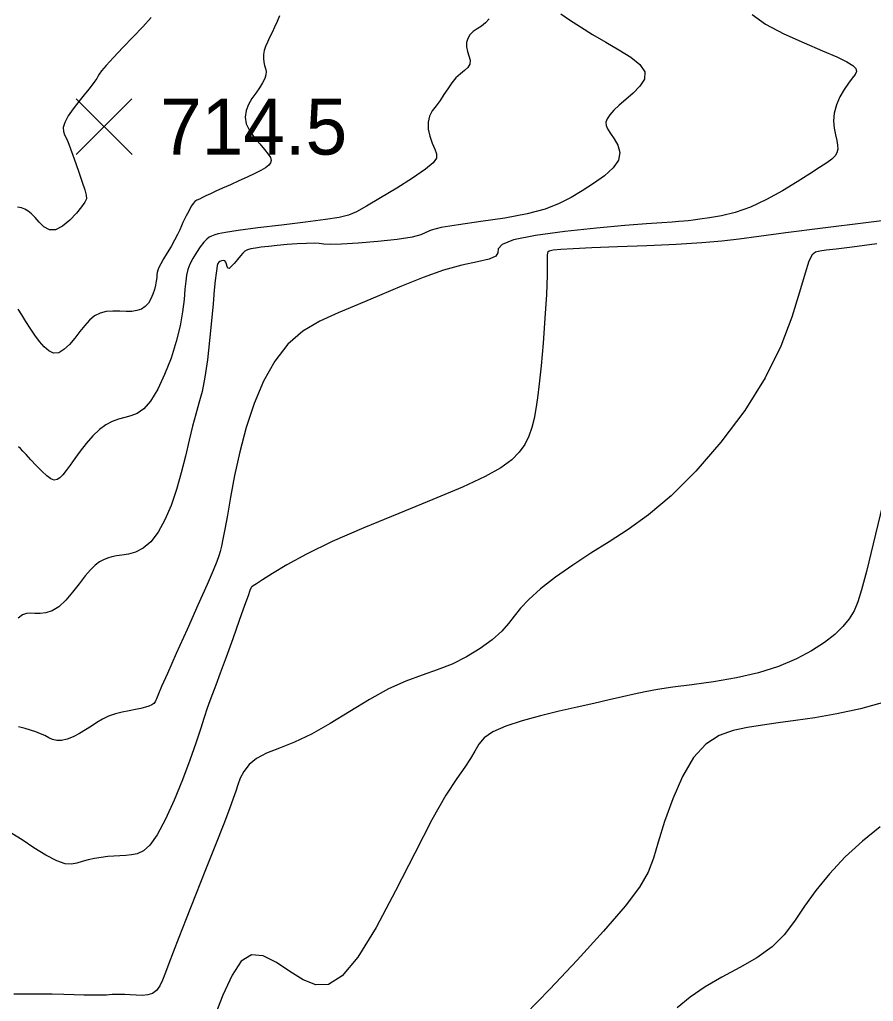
# Model space of a CAD drawing. Extents: x 2566142 to 2571431, y 418755 to 421584.
# Drawn here: x 2567768.3 to 2567997.3, y 419211.1 to 419474.5 of the extents above; entities that cross this region are included whole.
import ezdxf

# ---------------------------------------------------------------- set-up
doc = ezdxf.new("R2010")
doc.units = 0
for name, color, linetype in [('Contour_ADS_Major', 7, 'Continuous'), ('Contour_ADS_Minor', 7, 'Continuous'), ('Contour_ADS_Spot_Elevation', 7, 'Continuous')]:
    doc.layers.add(name, color=color, linetype=linetype)

# ---------------------------------------------------------------- blocks, each defined once
blk = doc.blocks.new('S750')
at = {"layer": 'Contour_ADS_Spot_Elevation'}
for p, q in [((-0.5, 0.498), (0.5, -0.498)), ((-0.498, -0.5), (0.498, 0.5))]:
    blk.add_line(p, q, dxfattribs=at)

msp = doc.modelspace()

# ---------------------------------------------------------------- linework, layer by layer
at = {"layer": 'Contour_ADS_Major'}
for points in [[(2567913.5, 419476), (2567915.82, 419474.42), (2567918.7, 419472.54), (2567921.98, 419470.49), (2567925.49, 419468.4), (2567929.03, 419466.37), (2567932.23, 419464.38), (2567934.69, 419462.43), (2567936, 419460.48), (2567935.89, 419458.53), (2567934.68, 419456.61), (2567932.85, 419454.76), (2567930.86, 419453.05), (2567929.1, 419451.5), (2567927.67, 419450.13), (2567926.59, 419448.92), (2567925.88, 419447.87), (2567925.55, 419446.96), (2567925.6, 419446.08), (2567926.01, 419445.12), (2567926.78, 419443.95), (2567927.81, 419442.49), (2567928.79, 419440.77), (2567929.31, 419438.85), (2567928.97, 419436.8), (2567927.5, 419434.69), (2567925.14, 419432.58), (2567922.26, 419430.51), (2567919.2, 419428.55), (2567916.22, 419426.74), (2567913.03, 419425.09), (2567909.23, 419423.62), (2567904.43, 419422.33), (2567898.45, 419421.22), (2567892, 419420.26), (2567885.99, 419419.43), (2567881.36, 419418.67), (2567878.7, 419417.98), (2567877.25, 419417.32), (2567875.92, 419416.69), (2567873.6, 419416.07)], [(2567873.6, 419416.07), (2567869.56, 419415.46), (2567864.41, 419414.91), (2567859.12, 419414.47), (2567854.66, 419414.21), (2567851.72, 419414.17), (2567849.94, 419414.26), (2567848.67, 419414.4), (2567847.27, 419414.48), (2567845.25, 419414.44), (2567842.75, 419414.3), (2567840.04, 419414.09), (2567837.4, 419413.86), (2567835.08, 419413.63), (2567833.13, 419413.41), (2567831.53, 419413.18), (2567830.3, 419412.94), (2567829.4, 419412.67), (2567828.73, 419412.31), (2567828.15, 419411.8), (2567827.51, 419411.07), (2567826.73, 419410.1), (2567825.89, 419409.07), (2567825.09, 419408.21), (2567824.48, 419407.74), (2567824.12, 419407.81), (2567823.94, 419408.27), (2567823.83, 419408.88), (2567823.65, 419409.43), (2567823.33, 419409.73), (2567822.9, 419409.8), (2567822.44, 419409.72), (2567822.03, 419409.56), (2567821.73, 419409.36), (2567821.51, 419409.05), (2567821.33, 419408.53), (2567821.18, 419407.68), (2567821, 419406.4), (2567820.79, 419404.51), (2567820.52, 419401.85), (2567820.18, 419398.24), (2567819.76, 419393.62), (2567819.25, 419388.42), (2567818.66, 419383.2), (2567817.98, 419378.5), (2567817.23, 419374.71), (2567816.41, 419371.56), (2567815.55, 419368.6), (2567814.66, 419365.4), (2567813.74, 419361.62), (2567812.76, 419357.38), (2567811.67, 419352.91), (2567810.41, 419348.42), (2567808.93, 419344.14), (2567807.27, 419340.26), (2567805.45, 419336.94), (2567803.5, 419334.37), (2567801.45, 419332.65), (2567799.41, 419331.64), (2567797.47, 419331.1), (2567795.72, 419330.82), (2567794.25, 419330.59), (2567793, 419330.35), (2567791.89, 419330.03), (2567790.82, 419329.58), (2567789.73, 419328.96), (2567788.56, 419328.07), (2567787.29, 419326.85), (2567785.86, 419325.21), (2567784.25, 419323.14), (2567782.51, 419320.88), (2567780.7, 419318.72), (2567778.87, 419316.97), (2567777.07, 419315.86), (2567775.36, 419315.29), (2567773.79, 419315.11), (2567772.4, 419315.14), (2567771.23, 419315.21), (2567770.16, 419315.15), (2567769.09, 419314.77), (2567767.89, 419313.87)], [(2568000.29, 419291.32), (2567993.82, 419289.55), (2567987.49, 419288.21), (2567981.61, 419287.19), (2567976.4, 419286.41), (2567971.77, 419285.77), (2567967.55, 419285.18), (2567963.57, 419284.54), (2567959.69, 419283.72), (2567955.94, 419282.37), (2567952.39, 419280.11), (2567949.08, 419276.53), (2567946.09, 419271.45), (2567943.48, 419265.45), (2567941.29, 419259.32), (2567939.6, 419253.82), (2567938.32, 419249.49), (2567936.88, 419245.74), (2567934.59, 419241.74), (2567930.75, 419236.63), (2567924.93, 419229.89), (2567917.85, 419222.15), (2567910.51, 419214.39), (2567903.9, 419207.56)]]:
    msp.add_lwpolyline(points, dxfattribs=at)
at = {"layer": 'Contour_ADS_Minor'}
for points in [[(2567838.05, 419475.5), (2567837.39, 419473.99), (2567836.71, 419472.46), (2567836.03, 419470.99), (2567835.36, 419469.64), (2567834.75, 419468.41), (2567834.25, 419467.26), (2567833.9, 419466.16), (2567833.74, 419465.09), (2567833.73, 419464.06), (2567833.84, 419463.08), (2567834.03, 419462.17), (2567834.24, 419461.33), (2567834.39, 419460.51), (2567834.37, 419459.65), (2567834.08, 419458.66), (2567833.47, 419457.51), (2567832.61, 419456.2), (2567831.62, 419454.77), (2567830.61, 419453.26), (2567829.7, 419451.68), (2567829.04, 419450.04), (2567828.77, 419448.33), (2567829.05, 419446.54), (2567829.94, 419444.68), (2567831.24, 419442.83), (2567832.69, 419441.1), (2567834.01, 419439.6), (2567834.97, 419438.41), (2567835.55, 419437.46), (2567835.76, 419436.69), (2567835.62, 419436.03), (2567835.13, 419435.39), (2567834.27, 419434.73), (2567833.03, 419434.01), (2567831.4, 419433.19), (2567829.37, 419432.24), (2567827.12, 419431.21), (2567824.84, 419430.18), (2567822.73, 419429.23), (2567820.95, 419428.41), (2567819.49, 419427.72), (2567818.29, 419427.15), (2567817.33, 419426.7), (2567816.53, 419426.34), (2567815.88, 419426.01), (2567815.33, 419425.64), (2567814.85, 419425.17), (2567814.42, 419424.55), (2567814.02, 419423.84), (2567813.65, 419423.11), (2567813.32, 419422.43), (2567813.02, 419421.85), (2567812.73, 419421.32), (2567812.43, 419420.75), (2567812.1, 419420.05), (2567811.72, 419419.17), (2567811.24, 419418.08), (2567810.64, 419416.78), (2567809.87, 419415.28), (2567808.92, 419413.6), (2567807.9, 419411.88), (2567806.93, 419410.26), (2567806.14, 419408.92), (2567805.63, 419407.94), (2567805.35, 419407.24), (2567805.21, 419406.66), (2567805.14, 419406.04), (2567805.07, 419405.27), (2567804.95, 419404.33), (2567804.76, 419403.26), (2567804.48, 419402.07), (2567804.07, 419400.81), (2567803.53, 419399.55), (2567802.84, 419398.4), (2567801.99, 419397.46), (2567800.97, 419396.8), (2567799.78, 419396.4), (2567798.41, 419396.2), (2567796.86, 419396.16), (2567795.15, 419396.22), (2567793.35, 419396.26), (2567791.56, 419396.15), (2567789.89, 419395.75), (2567788.41, 419394.96), (2567787.06, 419393.82), (2567785.77, 419392.4), (2567784.46, 419390.75), (2567783.08, 419388.99), (2567781.65, 419387.3)], [(2567964.81, 419475.87), (2567968.36, 419473.26), (2567973.29, 419470.65), (2567978.7, 419468.22), (2567983.68, 419466.11), (2567987.49, 419464.45), (2567990.13, 419463.17), (2567991.77, 419462.17), (2567992.58, 419461.34), (2567992.73, 419460.56), (2567992.37, 419459.73), (2567991.61, 419458.72), (2567990.59, 419457.41), (2567989.45, 419455.72), (2567988.32, 419453.74), (2567987.38, 419451.59), (2567986.77, 419449.41), (2567986.6, 419447.31), (2567986.76, 419445.36), (2567987.09, 419443.58), (2567987.45, 419442.04), (2567987.68, 419440.75), (2567987.72, 419439.67), (2567987.52, 419438.74), (2567987.01, 419437.88), (2567986.14, 419437.01), (2567984.8, 419436.01)], [(2567803.57, 419475.01), (2567801.32, 419472.56), (2567798.73, 419469.82), (2567796.02, 419466.98), (2567793.51, 419464.33), (2567791.52, 419462.17), (2567790.29, 419460.72), (2567789.64, 419459.82), (2567789.3, 419459.21), (2567789, 419458.66), (2567788.52, 419457.95), (2567787.81, 419457.01), (2567786.85, 419455.81), (2567785.63, 419454.3), (2567784.18, 419452.5), (2567782.67, 419450.55), (2567781.35, 419448.62), (2567780.41, 419446.89), (2567780.02, 419445.52), (2567780.07, 419444.43), (2567780.39, 419443.55), (2567780.8, 419442.76), (2567781.17, 419441.98), (2567781.54, 419441.04), (2567781.98, 419439.8), (2567782.57, 419438.09), (2567783.37, 419435.84), (2567784.26, 419433.31), (2567785.12, 419430.85), (2567785.8, 419428.8), (2567786.2, 419427.4), (2567786.23, 419426.41), (2567785.83, 419425.48), (2567784.93, 419424.27), (2567783.52, 419422.56), (2567781.75, 419420.66), (2567779.83, 419419.01), (2567777.95, 419418.04)], [(2567894.24, 419474.69), (2567893.26, 419473.56), (2567892.14, 419472.72), (2567890.99, 419472.01)], [(2567890.99, 419472.01), (2567889.93, 419471.28), (2567889.08, 419470.42), (2567888.48, 419469.41), (2567888.15, 419468.31), (2567888.14, 419467.13), (2567888.42, 419465.91), (2567888.82, 419464.71), (2567889.12, 419463.57), (2567889.08, 419462.55), (2567888.56, 419461.66), (2567887.65, 419460.82), (2567886.52, 419459.91), (2567885.33, 419458.82), (2567884.21, 419457.47), (2567883.15, 419455.93), (2567882.12, 419454.33), (2567881.07, 419452.77), (2567879.99, 419451.33), (2567878.99, 419449.95), (2567878.23, 419448.52), (2567877.84, 419446.92), (2567877.92, 419445.1), (2567878.36, 419443.18), (2567878.99, 419441.33), (2567879.64, 419439.73), (2567880.12, 419438.46), (2567880.1, 419437.33), (2567879.23, 419436.03), (2567877.16, 419434.3), (2567873.72, 419431.95), (2567869.46, 419429.26), (2567865.09, 419426.62), (2567861.34, 419424.41), (2567858.68, 419422.91), (2567856.51, 419421.98), (2567854.01, 419421.36), (2567850.33, 419420.81), (2567844.94, 419420.13), (2567838.57, 419419.35), (2567832.23, 419418.57), (2567826.95, 419417.89), (2567823.5, 419417.39), (2567821.58, 419417.02), (2567820.67, 419416.77), (2567820.21, 419416.57), (2567819.75, 419416.37), (2567819.18, 419416.07), (2567818.5, 419415.57), (2567817.68, 419414.74), (2567816.72, 419413.52), (2567815.72, 419412.02), (2567814.78, 419410.41), (2567814, 419408.83), (2567813.46, 419407.4), (2567813.11, 419405.94), (2567812.87, 419404.26), (2567812.66, 419402.14), (2567812.4, 419399.41), (2567811.99, 419396.1), (2567811.33, 419392.32), (2567810.33, 419388.12), (2567808.92, 419383.66), (2567807.21, 419379.26), (2567805.34, 419375.29), (2567803.43, 419372.13), (2567801.61, 419370.05), (2567799.87, 419368.83), (2567798.17, 419368.17), (2567796.51, 419367.76), (2567794.84, 419367.3), (2567793.15, 419366.67), (2567791.45, 419365.76), (2567789.7, 419364.48), (2567787.93, 419362.78), (2567786.19, 419360.79), (2567784.55, 419358.7), (2567783.08, 419356.71), (2567781.83, 419354.97), (2567780.78, 419353.52), (2567779.88, 419352.37), (2567779.08, 419351.55), (2567778.34, 419351.05), (2567777.56, 419350.94), (2567776.67, 419351.25), (2567775.58, 419352.04), (2567774.24, 419353.3), (2567772.76, 419354.84), (2567771.33, 419356.41), (2567770.09, 419357.77), (2567769.17, 419358.73), (2567768.52, 419359.38), (2567768.03, 419359.84)], [(2567984.8, 419436.01), (2567982.87, 419434.75), (2567980.24, 419433.08), (2567976.84, 419430.93), (2567972.88, 419428.53), (2567968.63, 419426.18), (2567964.33, 419424.19), (2567960.24, 419422.76), (2567956.52, 419421.85), (2567953.31, 419421.29), (2567950.77, 419420.95), (2567948.96, 419420.7), (2567947.64, 419420.51), (2567946.47, 419420.37), (2567945.13, 419420.26), (2567943.28, 419420.15), (2567940.53, 419419.98), (2567936.46, 419419.7), (2567930.66, 419419.22), (2567923.01, 419418.51), (2567914.57, 419417.59), (2567906.71, 419416.52), (2567900.77, 419415.35), (2567897.69, 419414.15), (2567896.68, 419412.97), (2567896.53, 419411.88), (2567896.04, 419410.96), (2567894.23, 419410.22), (2567891.11, 419409.5), (2567886.95, 419408.57), (2567882, 419407.21), (2567876.51, 419405.3), (2567870.71, 419402.98), (2567864.84, 419400.49), (2567859.12, 419398.06), (2567853.75, 419395.83), (2567848.8, 419393.54), (2567844.3, 419390.84), (2567840.28, 419387.36), (2567836.78, 419382.86), (2567833.76, 419377.48), (2567831.21, 419371.45), (2567829.08, 419365.04), (2567827.35, 419358.49), (2567825.97, 419352.15), (2567824.88, 419346.38), (2567824.03, 419341.51), (2567823.37, 419337.81), (2567822.85, 419335.12), (2567822.45, 419333.19), (2567822.11, 419331.78), (2567821.76, 419330.57), (2567821.22, 419329.06), (2567820.23, 419326.69), (2567818.57, 419322.88), (2567816.11, 419317.34), (2567813.21, 419310.83), (2567810.33, 419304.38), (2567807.95, 419299.02), (2567806.4, 419295.52), (2567805.56, 419293.58), (2567805.18, 419292.67), (2567805.03, 419292.24), (2567804.87, 419291.85), (2567804.63, 419291.43), (2567804.27, 419291.01), (2567803.74, 419290.61), (2567803, 419290.27), (2567802.03, 419289.97), (2567800.82, 419289.68), (2567799.37, 419289.39), (2567797.68, 419289.07), (2567795.84, 419288.69), (2567793.98, 419288.21), (2567792.19, 419287.59), (2567790.56, 419286.82), (2567789.04, 419285.93), (2567787.55, 419284.95), (2567786.01, 419283.94), (2567784.37, 419282.95), (2567782.68, 419282.07), (2567781.05, 419281.4), (2567779.57, 419281.04), (2567778.29, 419281.05), (2567777.16, 419281.35), (2567776.11, 419281.83), (2567775.05, 419282.37), (2567773.9, 419282.88), (2567772.65, 419283.36), (2567771.27, 419283.81), (2567769.76, 419284.26), (2567768.05, 419284.71)], [(2567777.95, 419418.04), (2567776.28, 419418.08), (2567774.82, 419418.88), (2567773.55, 419420.09), (2567772.45, 419421.35), (2567771.47, 419422.35), (2567770.57, 419423.09), (2567769.7, 419423.61), (2567768.8, 419423.96), (2567767.77, 419424.17)], [(2568006.58, 419421.35), (2567995.23, 419419.93), (2567983.74, 419418.54), (2567973.8, 419417.3), (2567966.59, 419416.32), (2567961.3, 419415.57), (2567956.64, 419415), (2567951.31, 419414.55), (2567944.39, 419414.15), (2567936.5, 419413.81)], [(2567936.5, 419413.81), (2567928.64, 419413.5), (2567921.82, 419413.24), (2567916.81, 419413), (2567913.48, 419412.78), (2567911.45, 419412.57), (2567910.37, 419412.35), (2567909.89, 419412.03), (2567909.77, 419411.19), (2567909.81, 419409.33), (2567909.8, 419405.93), (2567909.58, 419400.72), (2567909.18, 419394.35), (2567908.68, 419387.69), (2567908.16, 419381.59), (2567907.68, 419376.74), (2567907.24, 419373), (2567906.78, 419370.02), (2567906.27, 419367.46), (2567905.66, 419365.06), (2567904.86, 419362.74), (2567903.78, 419360.52), (2567902.31, 419358.41), (2567900.3, 419356.37), (2567897.39, 419354.25), (2567893.14, 419351.88), (2567887.12, 419349.07), (2567879.16, 419345.7), (2567870, 419341.97), (2567860.67, 419338.13), (2567852.14, 419334.42), (2567845.24, 419331.09), (2567839.95, 419328.22), (2567836.09, 419325.9), (2567833.44, 419324.18), (2567831.8, 419323.11), (2567830.92, 419322.54), (2567830.55, 419322.28), (2567830.43, 419322.16), (2567830.33, 419321.96), (2567830.09, 419321.32), (2567829.57, 419319.88), (2567828.63, 419317.25), (2567827.19, 419313.24), (2567825.46, 419308.39), (2567823.68, 419303.44), (2567822.1, 419299.11), (2567820.91, 419295.93), (2567820.03, 419293.62), (2567819.32, 419291.72), (2567818.63, 419289.73), (2567817.84, 419287.24), (2567816.84, 419284.13), (2567815.58, 419280.34), (2567813.97, 419275.78), (2567811.98, 419270.53), (2567809.75, 419265.04), (2567807.45, 419259.93), (2567805.24, 419255.78), (2567803.26, 419253.02), (2567801.49, 419251.45), (2567799.86, 419250.71), (2567798.3, 419250.42), (2567796.76, 419250.26), (2567795.2, 419250.16), (2567793.6, 419250.05), (2567791.93, 419249.91), (2567790.18, 419249.69), (2567788.4, 419249.4), (2567786.69, 419249.04), (2567785.11, 419248.61), (2567783.69, 419248.16), (2567782.23, 419247.89), (2567780.51, 419248.02), (2567778.27, 419248.78), (2567775.38, 419250.3), (2567772.14, 419252.3), (2567768.95, 419254.38), (2567766.23, 419256.16)], [(2567998.17, 419414.31), (2567991.6, 419413.46), (2567987.27, 419412.91), (2567984.58, 419412.58), (2567982.93, 419412.36), (2567981.78, 419412.12), (2567980.87, 419411.39), (2567979.99, 419409.66)], [(2567979.99, 419409.66), (2567978.95, 419406.43), (2567977.51, 419401.33), (2567975.44, 419394.65), (2567972.45, 419386.84), (2567968.28, 419378.36), (2567962.79, 419369.64), (2567956.4, 419361.15), (2567949.63, 419353.37), (2567943.02, 419346.75), (2567937.01, 419341.61), (2567931.54, 419337.64), (2567926.42, 419334.37), (2567921.49, 419331.32), (2567916.64, 419328.14), (2567912.07, 419324.89), (2567908.05, 419321.76), (2567904.85, 419318.93), (2567902.61, 419316.53), (2567900.98, 419314.42), (2567899.47, 419312.43), (2567897.61, 419310.36), (2567895.03, 419308.09), (2567891.82, 419305.75), (2567888.17, 419303.51), (2567884.29, 419301.57), (2567880.32, 419300.01), (2567876.23, 419298.61), (2567871.89, 419297.02), (2567867.22, 419294.92), (2567862.16, 419292.1), (2567856.89, 419288.86), (2567851.63, 419285.6), (2567846.6, 419282.75), (2567842.02, 419280.6), (2567837.97, 419278.99), (2567834.55, 419277.63), (2567831.82, 419276.24), (2567829.83, 419274.61), (2567828.44, 419272.8), (2567827.5, 419270.94), (2567826.83, 419269.16), (2567826.26, 419267.49), (2567825.58, 419265.53), (2567824.58, 419262.77), (2567823.04, 419258.71), (2567820.82, 419253.06), (2567818.19, 419246.4), (2567815.46, 419239.54), (2567812.98, 419233.26), (2567811, 419228.19), (2567809.49, 419224.26), (2567808.33, 419221.22), (2567807.41, 419218.8), (2567806.63, 419216.82), (2567805.87, 419215.23), (2567805.02, 419214.03), (2567803.97, 419213.23), (2567802.66, 419212.82), (2567801.15, 419212.7), (2567799.55, 419212.75), (2567797.98, 419212.85), (2567796.53, 419212.93), (2567795.24, 419212.95), (2567794.1, 419212.94), (2567793.14, 419212.91), (2567792.35, 419212.85), (2567791.57, 419212.79), (2567790.63, 419212.74), (2567789.37, 419212.72), (2567787.65, 419212.74), (2567785.5, 419212.79), (2567782.97, 419212.86), (2567780.13, 419212.92), (2567777.06, 419212.98), (2567773.97, 419213.02), (2567771.09, 419213.04), (2567768.64, 419213.05), (2567766.78, 419213.04)], [(2567781.65, 419387.3), (2567780.21, 419385.93), (2567778.8, 419385.11), (2567777.44, 419385.02), (2567776.14, 419385.57), (2567774.87, 419386.64), (2567773.62, 419388.1), (2567772.38, 419389.81), (2567771.15, 419391.65), (2567769.98, 419393.5), (2567768.89, 419395.24), (2567767.89, 419396.79)], [(2567999.71, 419344.2), (2567997.19, 419333.83), (2567995.4, 419326.4), (2567994.14, 419321.47), (2567993.12, 419318.23), (2567992.09, 419315.88), (2567990.79, 419313.73), (2567989.1, 419311.62), (2567986.92, 419309.5), (2567984.16, 419307.34), (2567980.73, 419305.13), (2567976.63, 419302.95), (2567971.88, 419300.94), (2567966.49, 419299.22), (2567960.54, 419297.87), (2567954.43, 419296.84), (2567948.59, 419296.04), (2567943.48, 419295.36), (2567939.42, 419294.74), (2567936.1, 419294.12), (2567933.1, 419293.47), (2567929.98, 419292.75), (2567926.38, 419291.94), (2567922.31, 419291.03), (2567917.82, 419290.02), (2567913, 419288.9), (2567907.98, 419287.68), (2567903.08, 419286.36), (2567898.7, 419284.93), (2567895.22, 419283.41), (2567892.91, 419281.79), (2567891.44, 419280.06), (2567890.37, 419278.2), (2567889.26, 419276.2), (2567887.7, 419273.94), (2567885.53, 419270.87), (2567882.63, 419266.38), (2567878.89, 419259.8), (2567874.28, 419250.87), (2567869.15, 419240.73), (2567863.93, 419230.91), (2567859.06, 419222.92), (2567854.86, 419217.92), (2567851.19, 419215.65), (2567847.78, 419215.51), (2567844.38, 419216.88), (2567840.8, 419219.14), (2567837.16, 419221.53), (2567833.66, 419223.27), (2567830.48, 419223.58), (2567827.76, 419221.85), (2567825.3, 419218.15), (2567822.84, 419212.74), (2567820.11, 419205.88)], [(2567999.09, 419257.94), (2567994.34, 419254.09), (2567989.75, 419249.82), (2567985.51, 419245.34), (2567981.84, 419240.87), (2567978.82, 419236.61), (2567976.14, 419232.63), (2567973.37, 419228.97), (2567970.1, 419225.69), (2567966.04, 419222.79), (2567961.44, 419220.15), (2567956.68, 419217.61), (2567952.15, 419214.99), (2567948.15, 419212.21), (2567944.68, 419209.37)]]:
    msp.add_lwpolyline(points, dxfattribs=at)

# ---------------------------------------------------------------- block references
at = {"layer": 'Contour_ADS_Spot_Elevation', "xscale": 15, "yscale": 15}
msp.add_blockref('S750', (2567790.97, 419445.75), dxfattribs=at)

# ---------------------------------------------------------------- texts
at = {"layer": 'Contour_ADS_Spot_Elevation'}
msp.add_text('714.5', height=15, dxfattribs=at).set_placement((2567805.97, 419438.25))

doc.saveas('drawing.dxf')
